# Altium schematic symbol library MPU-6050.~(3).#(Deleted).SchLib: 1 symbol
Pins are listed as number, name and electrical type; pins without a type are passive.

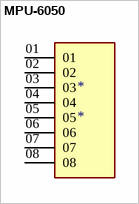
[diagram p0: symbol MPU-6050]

## MPU-6050
designator *
footprint MPU-6050
pins: 01, 02, 03, 04, 05, 06, 07, 08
